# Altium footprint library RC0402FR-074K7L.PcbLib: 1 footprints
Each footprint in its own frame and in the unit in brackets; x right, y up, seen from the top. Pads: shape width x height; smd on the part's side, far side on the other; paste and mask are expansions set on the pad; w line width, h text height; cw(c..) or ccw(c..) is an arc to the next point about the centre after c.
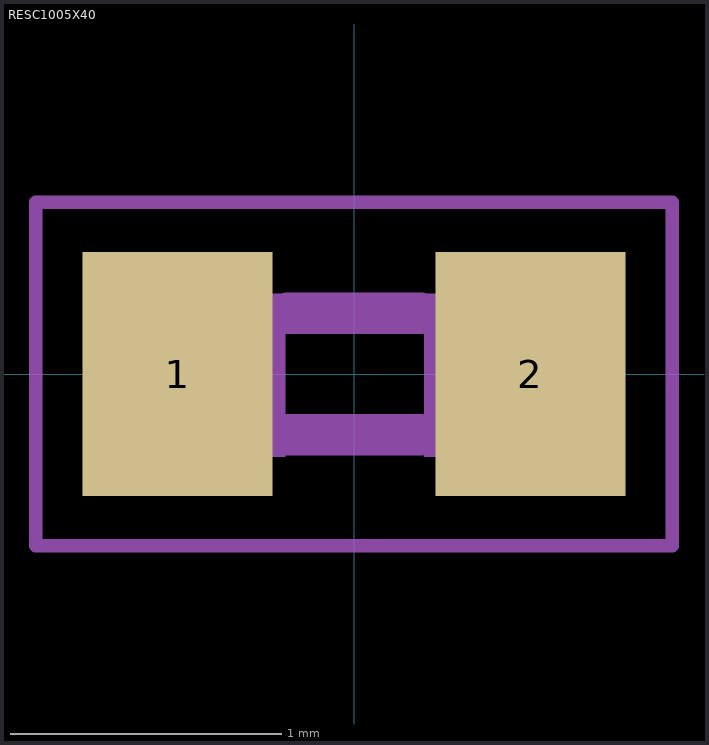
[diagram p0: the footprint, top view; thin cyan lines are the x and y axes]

## RESC1005X40 [mm]
pads (2):
  rect 0.7x0.9 smd: 1(-0.65,0) 2(0.65,0)
Assembly Top:
  region: 0.559,-0.305 0.259,-0.305 0.259,0.295 0.559,0.295
  region: -0.254,-0.305 -0.554,-0.305 -0.554,0.295 -0.254,0.295
  lines w0.152: -0.245,-0.224 0.245,-0.224 ; -0.245,0.224 0.245,0.224
Courtyard Top:
  lines w0.051: -1.173,-0.633 -1.173,0.633 1.173,0.633 1.173,-0.633 -1.173,-0.633
3D body "step_temp.STEP": height 0.4, standoff 0, extent -0.5,-0.25 0.5,0.25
